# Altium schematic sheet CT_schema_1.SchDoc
size 547 x 490 mm
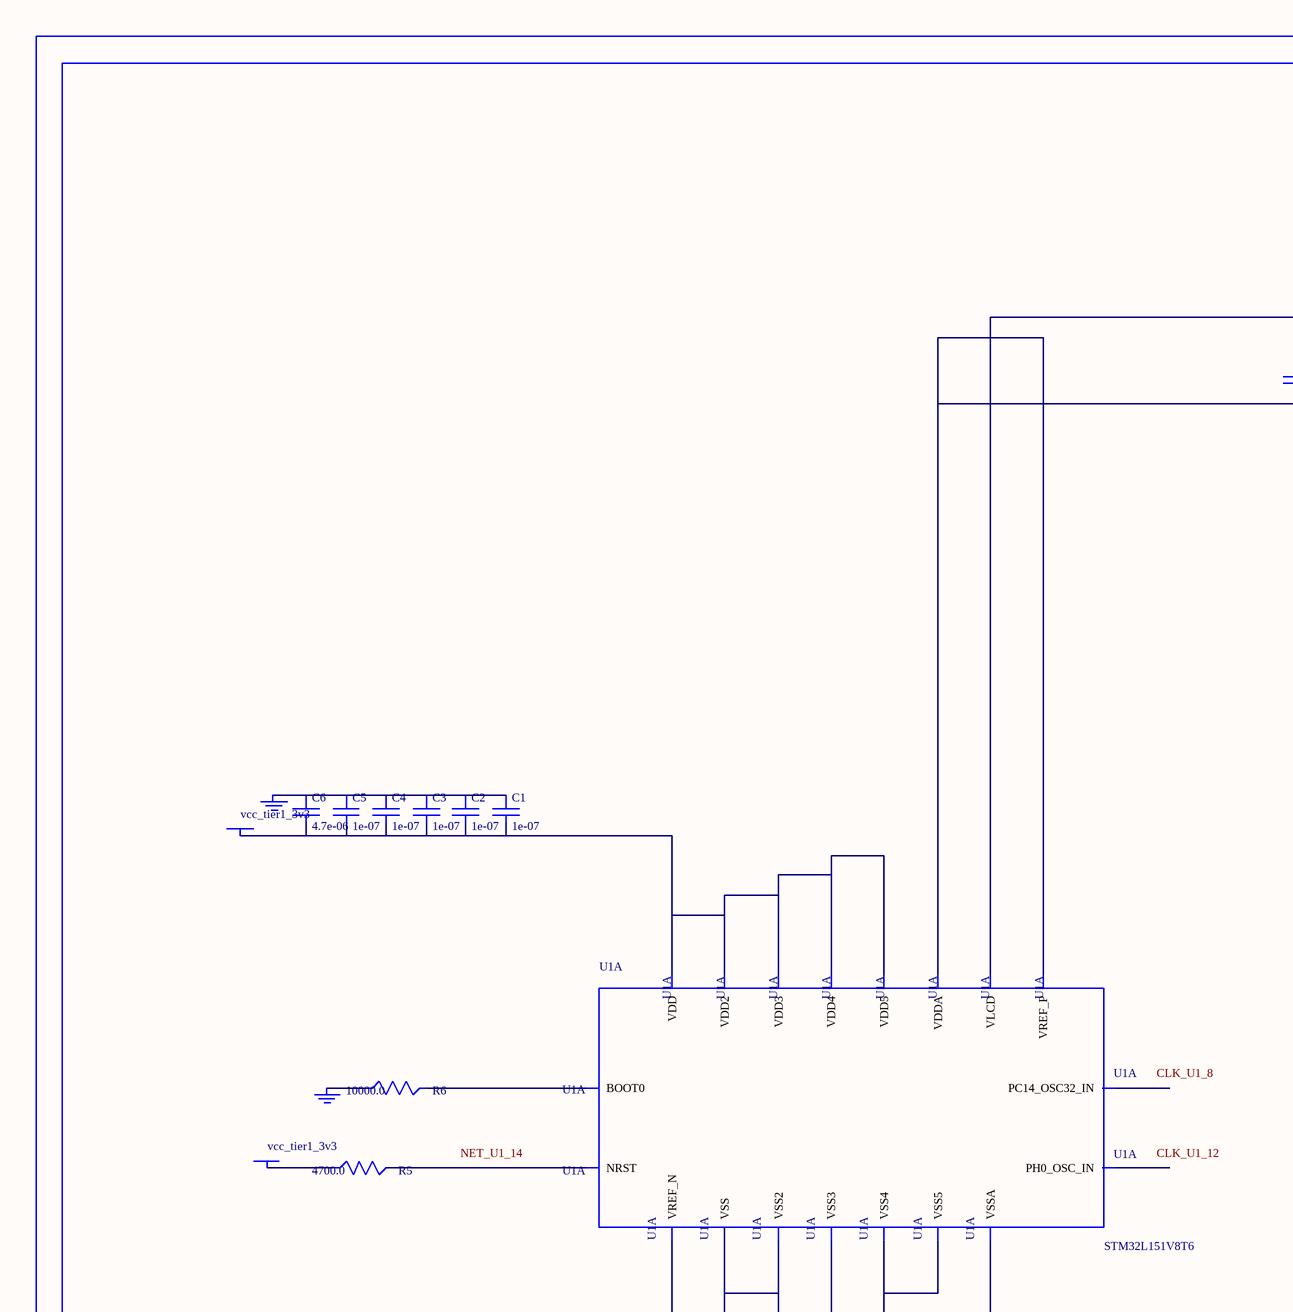
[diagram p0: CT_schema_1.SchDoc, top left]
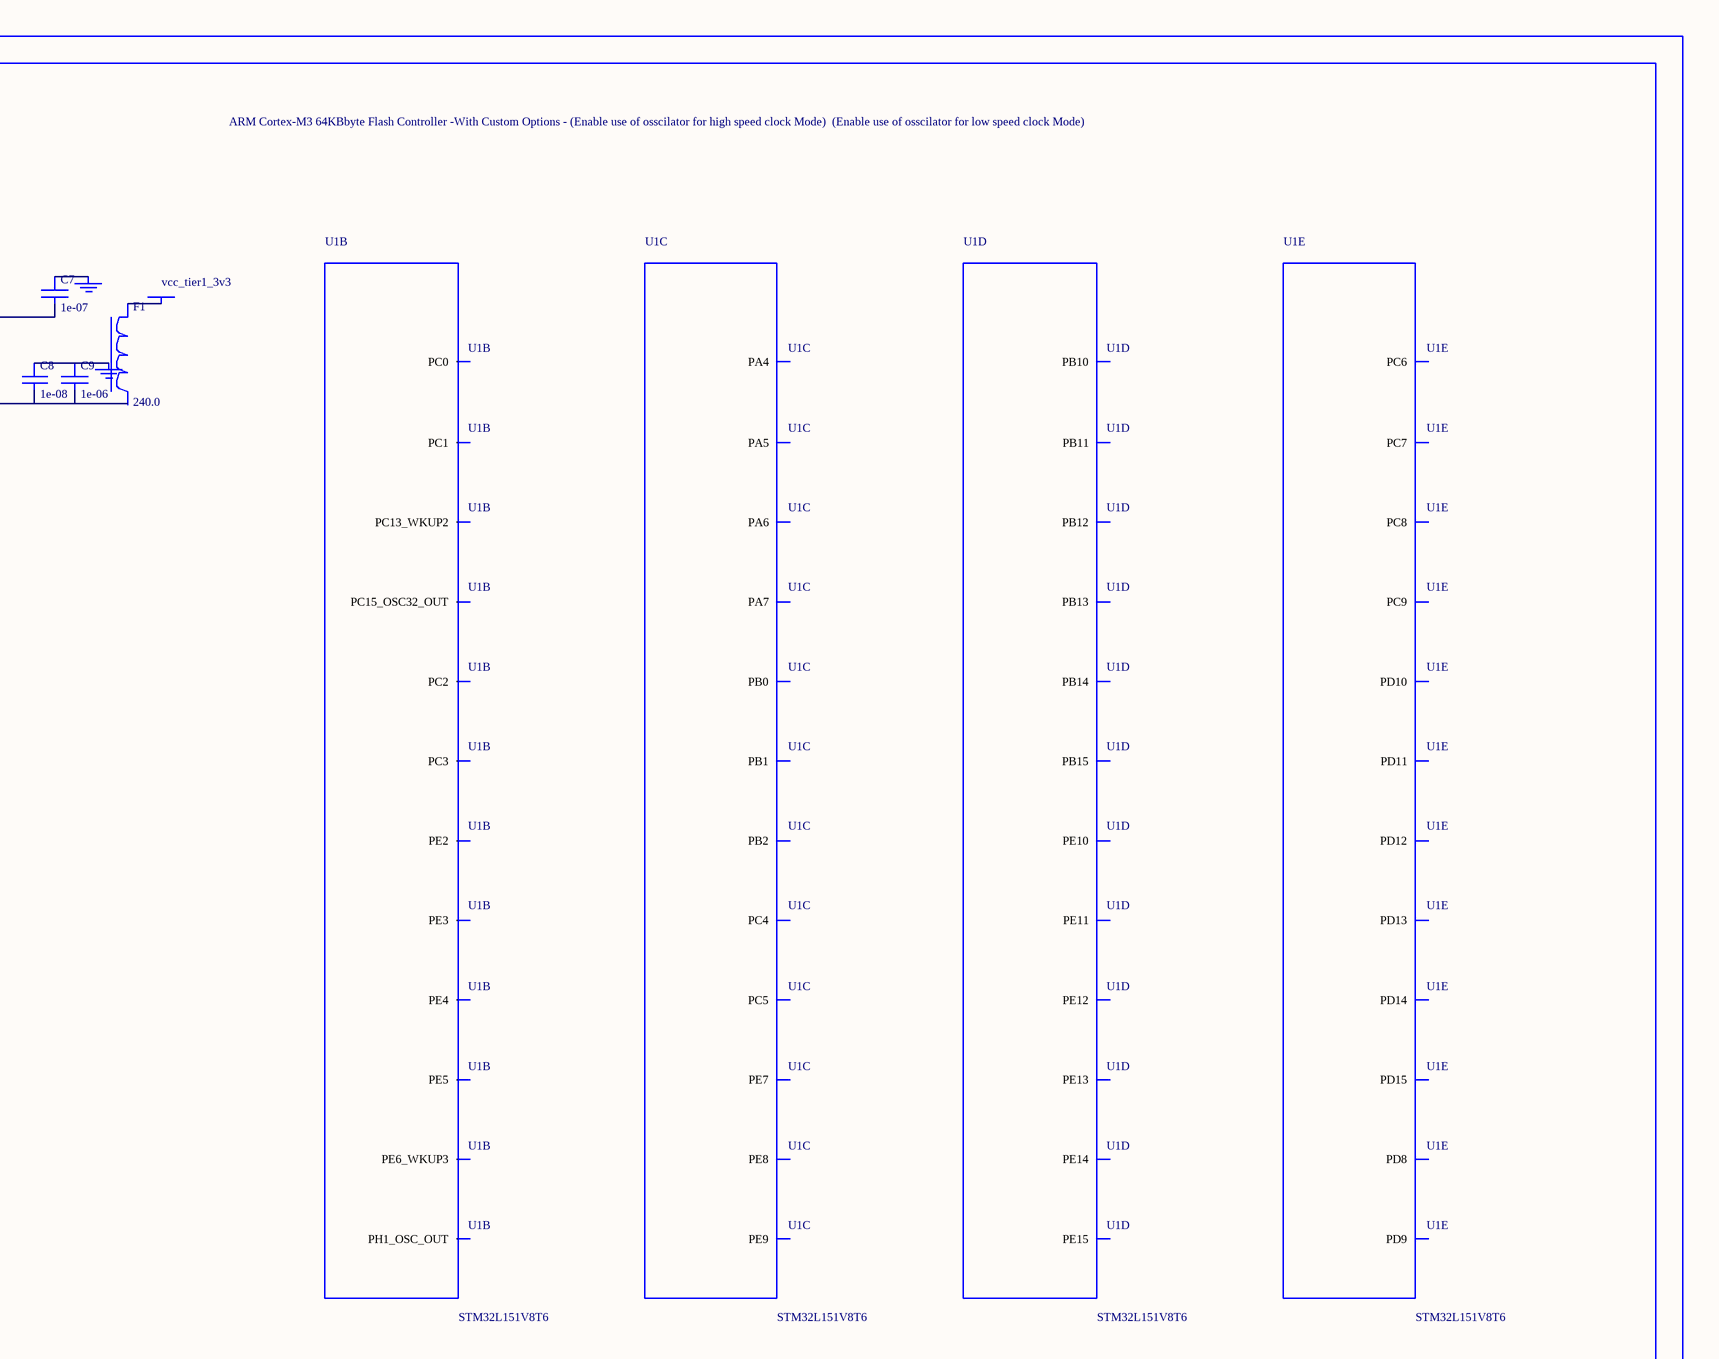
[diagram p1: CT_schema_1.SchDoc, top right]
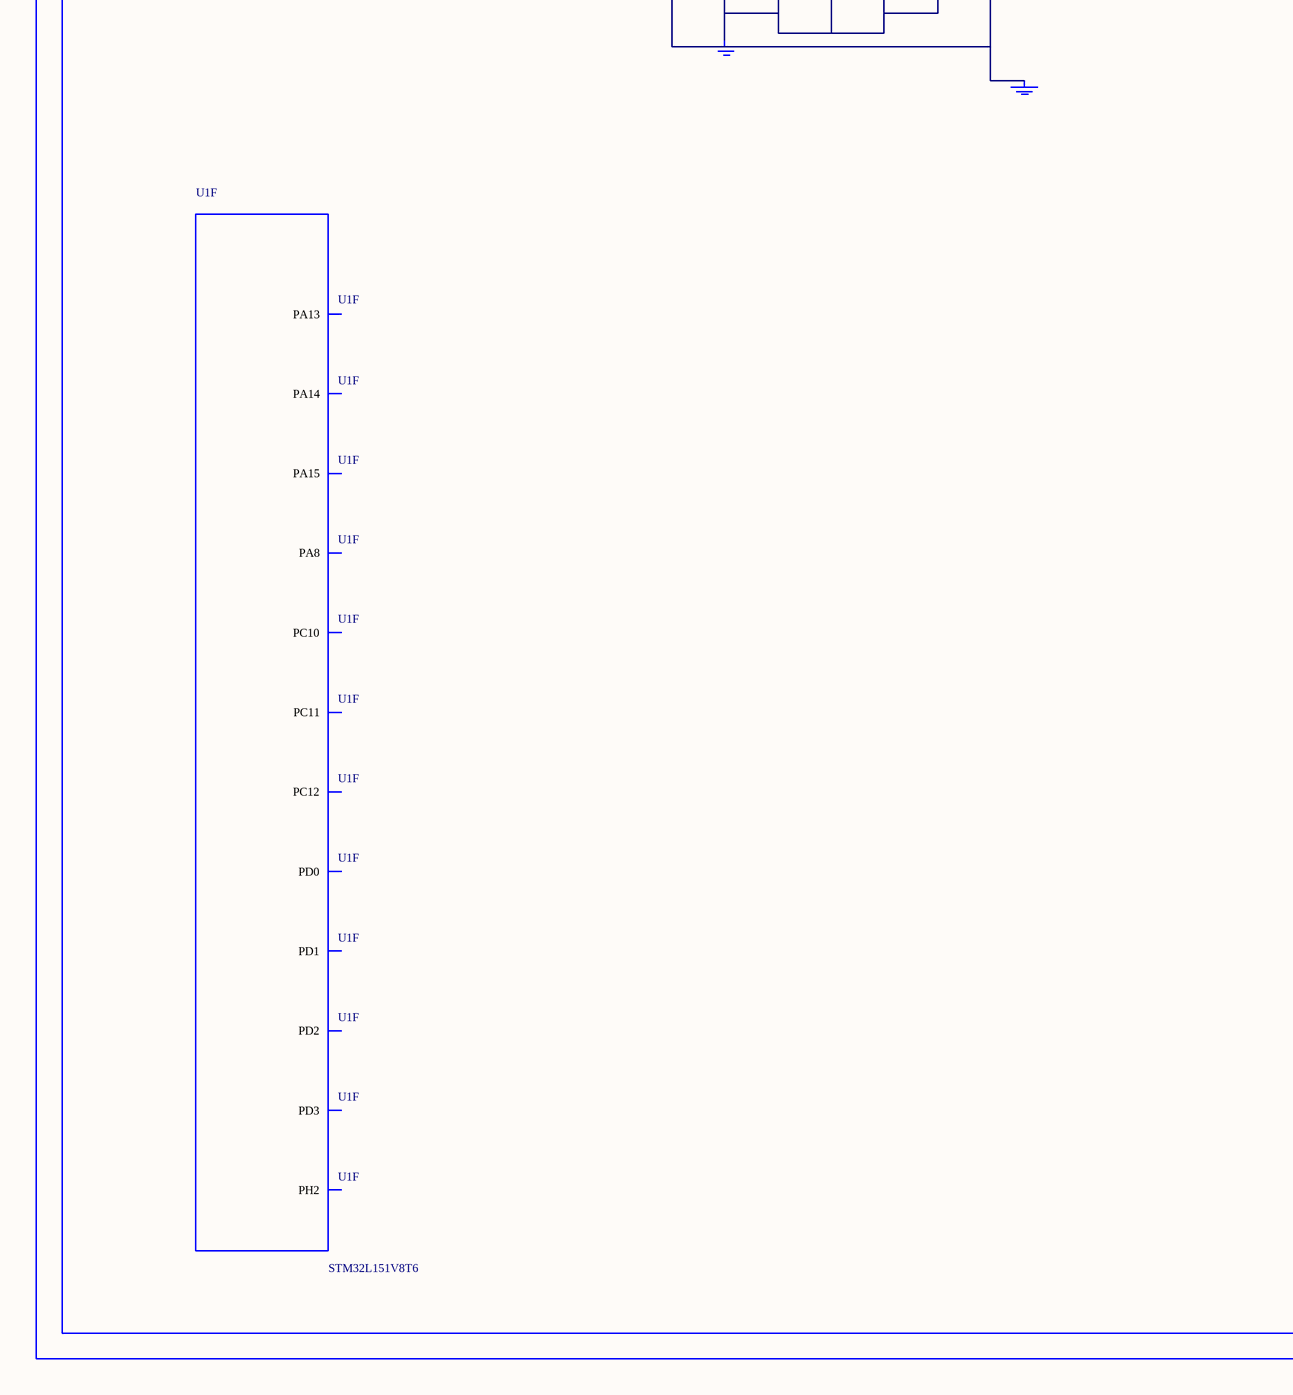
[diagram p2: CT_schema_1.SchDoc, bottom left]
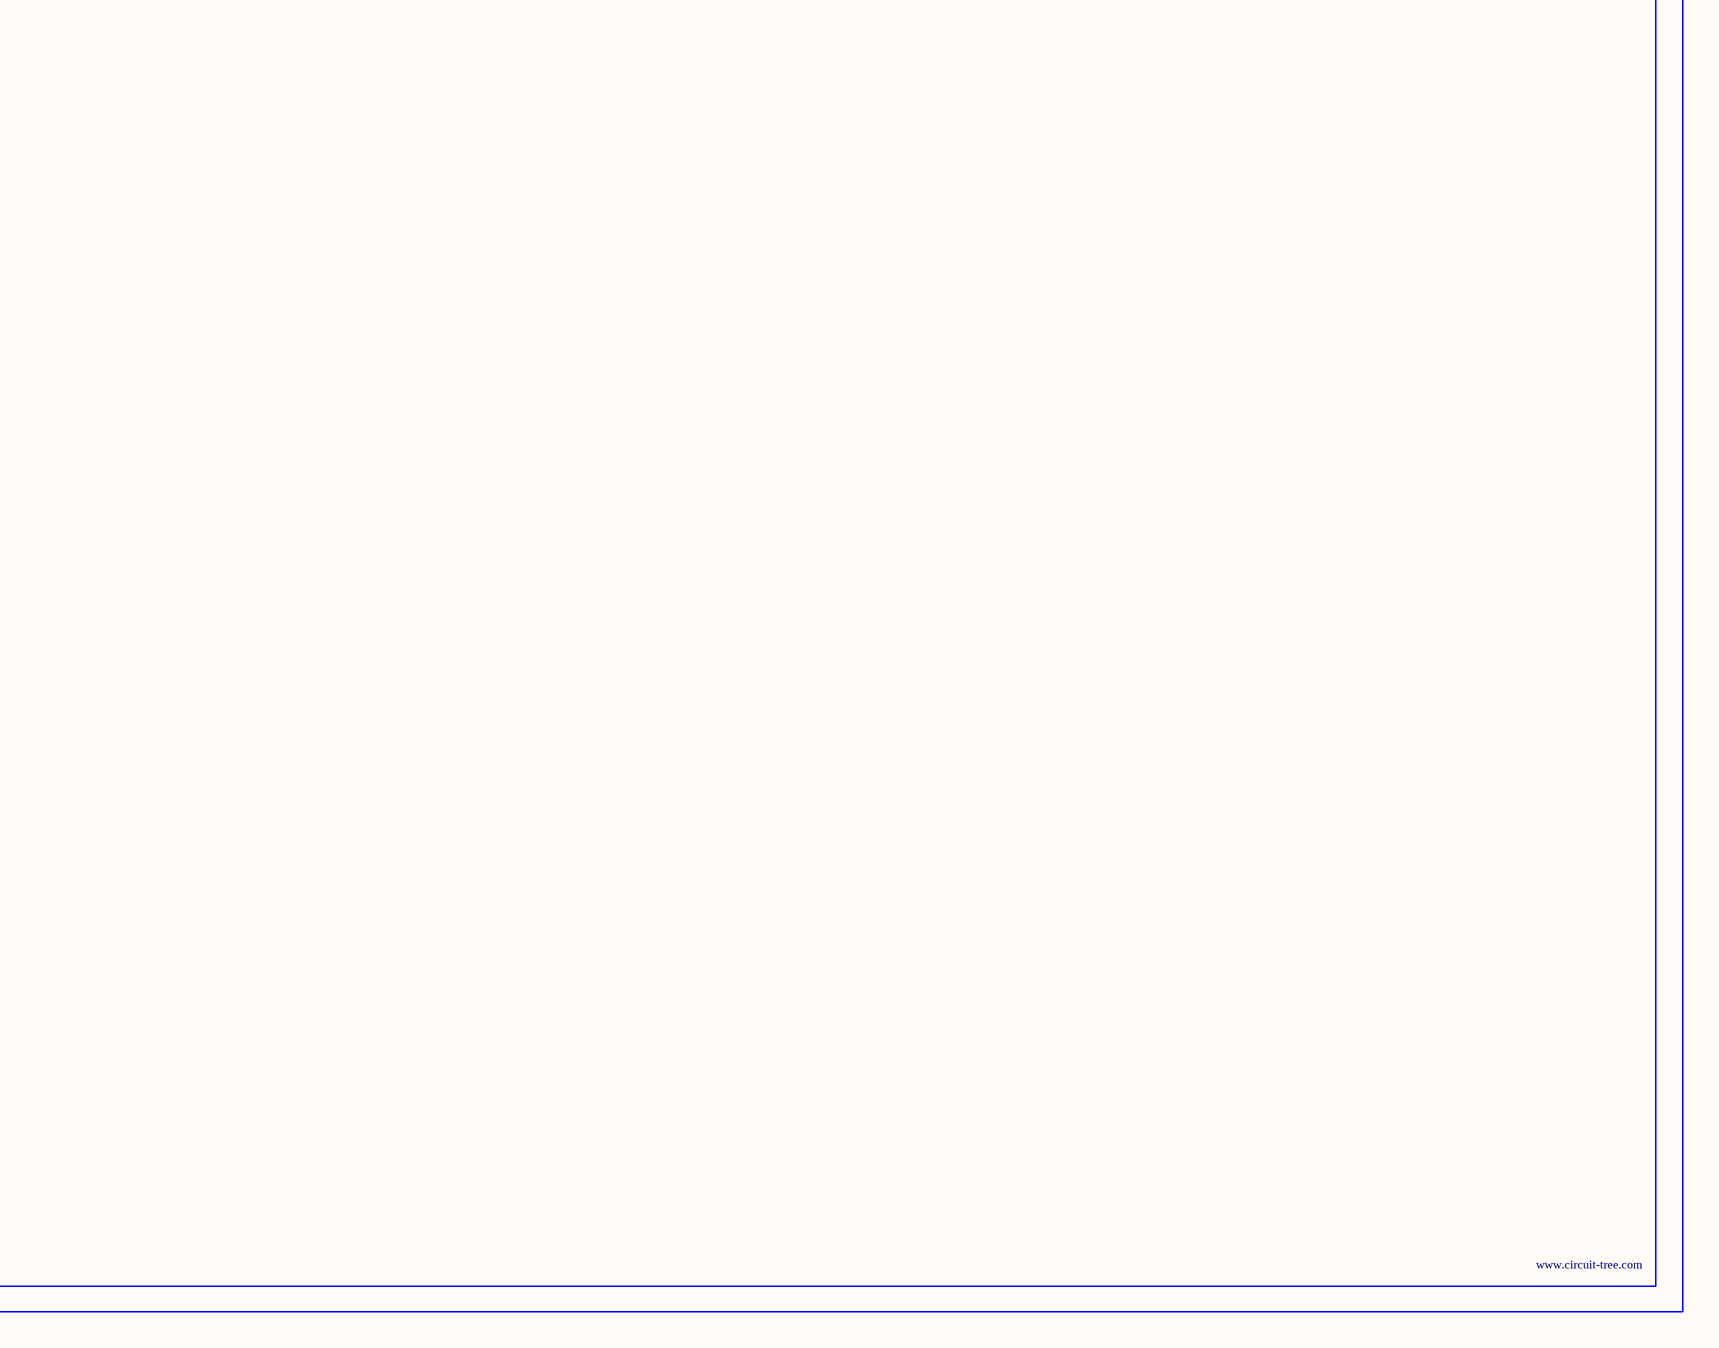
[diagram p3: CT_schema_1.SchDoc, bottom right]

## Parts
BORDER0  (no value)
C1  1e-07  [C0603]
C2  1e-07  [C0603]
C3  1e-07  [C0603]
C4  1e-07  [C0603]
C5  1e-07  [C0603]
C6  4.7e-06  [C0603]
C7  1e-07  [C0603]
C8  1e-08  [C0603]
C9  1e-06  [C0603]
F1  240.0  [L0603]
GND_INSTANCE_0_0  (no value)
GND_INSTANCE_0_1  (no value)
GND_INSTANCE_0_2  (no value)
GND_INSTANCE_0_3  (no value)
GND_INSTANCE_0_4  (no value)
GND_INSTANCE_0_5  (no value)
POWER_INSTANCE_0_0  vcc_tier1_3v3
POWER_INSTANCE_0_1  vcc_tier1_3v3
POWER_INSTANCE_0_2  vcc_tier1_3v3
R5  4700.0  [R0603]
R6  10000.0  [R0603]
U1  STM32L151V8T6  [LQFP100]  (parts A,B,C,D,E,F of 7)

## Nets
NetC1_1: C1.1 C2.1 C3.1 C4.1 C5.1 C6.1 GND_INSTANCE_0_1.0(GND)
NetC1_2: C1.2 C2.2 C3.2 C4.2 C5.2 C6.2 POWER_INSTANCE_0_0.0(PWR) U1.11(VDD) U1.28(VDD2) U1.50(VDD3) U1.75(VDD4) U1.100(VDD5)
NetC7_1: C7.1 GND_INSTANCE_0_0.0(GND)
NetC7_2: C7.2 U1.6(VLCD)
NetC8_1: C8.1 C9.1 GND_INSTANCE_0_3.0(GND)
NetC8_2: C8.2 C9.2 U1.21(VREF_P) U1.22(VDDA)
NetF1_1: F1.1 POWER_INSTANCE_0_1.0(PWR)
NetGND_INSTANCE_0_2_0: GND_INSTANCE_0_2.0(GND) U1.19(VSSA) U1.20(VREF_N)
NetGND_INSTANCE_0_4_0: GND_INSTANCE_0_4.0(GND) R6.1
NetGND_INSTANCE_0_5_0: GND_INSTANCE_0_5.0(GND) U1.10(VSS) U1.27(VSS2) U1.49(VSS3) U1.74(VSS4) U1.99(VSS5)
NetPOWER_INSTANCE_0_2_0: POWER_INSTANCE_0_2.0(PWR) R5.1
NetR5_2: R5.2 U1.14(NRST)
NetR6_2: R6.2 U1.94(BOOT0)

Not connected (* = marked no-connect by the designer): F1 2; U1 1(PE2) 2(PE3) 3(PE4) 4(PE5) 5(PE6_WKUP3) 7(PC13_WKUP2) 8(PC14_OSC32_IN) 9(PC15_OSC32_OUT) 12(PH0_OSC_IN) 13(PH1_OSC_OUT) 15(PC0) 16(PC1) 17(PC2) 18(PC3) 29(PA4) 30(PA5) 31(PA6) 32(PA7) 33(PC4) 34(PC5) 35(PB0) 36(PB1) 37(PB2) 38(PE7) 39(PE8) 40(PE9) 41(PE10) 42(PE11) 43(PE12) 44(PE13) 45(PE14) 46(PE15) 47(PB10) 48(PB11) 51(PB12) 52(PB13) 53(PB14) 54(PB15) 55(PD8) 56(PD9) 57(PD10) 58(PD11) 59(PD12) 60(PD13) 61(PD14) 62(PD15) 63(PC6) 64(PC7) 65(PC8) 66(PC9) 67(PA8) 72(PA13) 73(PH2) 76(PA14) 77(PA15) 78(PC10) 79(PC11) 80(PC12) 81(PD0) 82(PD1) 83(PD2) 84(PD3)

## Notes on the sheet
- Labels drawn without touching a wire or pin: CLK_U1_8, CLK_U1_12, NET_U1_14

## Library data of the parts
BORDER0 = BORDER_PAGE0
C1-C5 C7 = 06035C104K4Z2A
C6 = GRM188R6YA475KE15D
C8 = 06035C103K4Z2A
C9 = C0603C105K3RACTU
F1 = Z0603C241ASMST
GND_INSTANCE_0_0-GND_INSTANCE_0_5 = GND
POWER_INSTANCE_0_0-POWER_INSTANCE_0_2 = PWR
R5 = RC0603JR-074K7L
R6 = RC0603JR-0710KL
